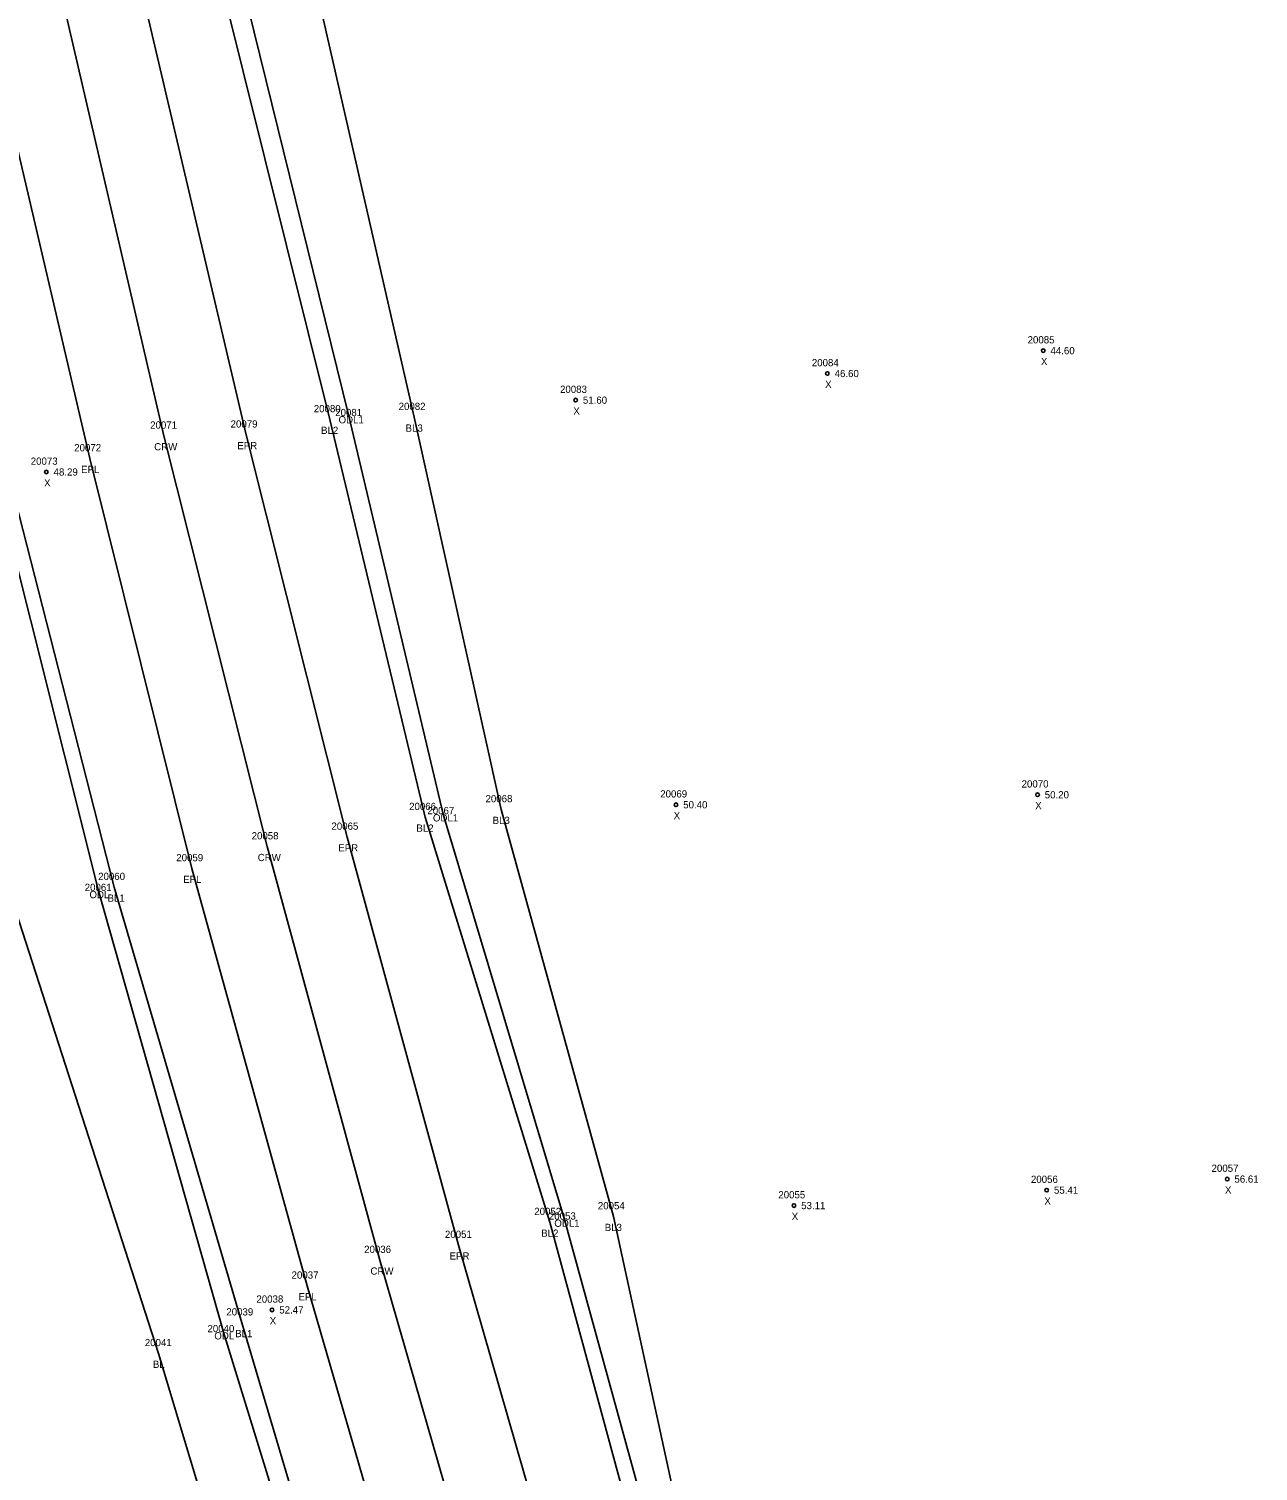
# Model space of a CAD drawing. Extents: x 2445178 to 2446260, y 791158 to 792318.
# Drawn here: x 2445750.9 to 2445920.9, y 791354.3 to 791553.6 of the extents above; entities that cross this region are included whole.
import ezdxf

# ---------------------------------------------------------------- set-up
doc = ezdxf.new("R2010")
doc.units = 0
for name, color, linetype in [('RD_DTM_BkLn1', 7, 'Continuous'), ('RD_EX_H2O', 7, 'Continuous'), ('RD_EX_H2O_txCode', 7, 'Continuous'), ('RD_EX_Road', 7, 'Continuous'), ('RD_EX_Road_txCode', 7, 'Continuous'), ('RD_Sketch8', 7, 'Continuous'), ('RD_SMD_Locator', 7, 'Continuous'), ('RD_SMD_Misc', 7, 'Continuous')]:
    doc.layers.add(name, color=color, linetype=linetype)

msp = doc.modelspace()

# ---------------------------------------------------------------- linework, layer by layer
at = {"layer": 'RD_DTM_BkLn1'}
for points in [[(2445860.1, 791179.04), (2445833.11, 791268.21), (2445816.53, 791324.11), (2445799.46, 791383.44), (2445783.89, 791440.59), (2445769.57, 791497.35), (2445755.95, 791556.11), (2445741.36, 791625.36), (2445732.84, 791671.31), (2445721.28, 791739.8), (2445717.39, 791765.43)], [(2445882.78, 791184.78), (2445856.18, 791275.27), (2445839.04, 791329.43), (2445822.96, 791388.68), (2445805.7, 791444.65), (2445792.52, 791499.62), (2445777.56, 791559.78), (2445760.75, 791635.11), (2445757, 791668.89), (2445761.65, 791682.26), (2445806.3, 791698.85), (2445844.78, 791714.67)], [(2445896.2, 791187.37), (2445865.75, 791277.36), (2445863.45, 791286.42), (2445844.64, 791330.14), (2445831.75, 791389.47), (2445816.24, 791445.72), (2445804.21, 791499.93), (2445790.09, 791561.7), (2445779.57, 791613.54), (2445773.51, 791630.61), (2445764.7, 791668.39), (2445768.27, 791675.25), (2445808.12, 791695.24), (2445844.78, 791714.67)], [(2445839.71, 791171.21), (2445812.99, 791261.63), (2445797.26, 791317.94), (2445780.39, 791374.8), (2445762.73, 791434.98), (2445748.42, 791490.93), (2445737.04, 791541.96), (2445736.07, 791553.56), (2445730.12, 791555.63), (2445697.6, 791546.96), (2445670.73, 791536.08)], [(2445828.38, 791169.47), (2445802.46, 791258.37), (2445786.04, 791313.32), (2445768.83, 791370.56), (2445749.12, 791431.66), (2445737.78, 791488.28), (2445729.51, 791541.48), (2445729.31, 791548.76), (2445698.8, 791542.8), (2445670.73, 791536.08)]]:
    msp.add_lwpolyline(points, dxfattribs=at)
at = {"layer": 'RD_EX_H2O'}
for points in [[(2445885.63, 791185.34), (2445858.54, 791275.66), (2445841.27, 791329.71), (2445824.98, 791389.05), (2445808.2, 791445.07), (2445795.15, 791500.08), (2445780.4, 791559.92), (2445764.43, 791632.51), (2445759.72, 791668.56), (2445764.88, 791679.11), (2445806.8, 791696.09), (2445844.78, 791714.67)], [(2445837.89, 791170.92), (2445811.42, 791261.06), (2445795.3, 791316.79), (2445777.82, 791373.49), (2445760.55, 791434.46), (2445746.47, 791490.55), (2445734.66, 791541.55), (2445732.29, 791551.98), (2445698.31, 791545.12), (2445670.73, 791536.08)]]:
    msp.add_lwpolyline(points, dxfattribs=at)
at = {"layer": 'RD_EX_Road'}
for points in [[(2445850.42, 791174.36), (2445823.13, 791264.7), (2445806.34, 791321.46), (2445789.41, 791379.89), (2445773.46, 791437.57), (2445759.36, 791494.22), (2445744.01, 791559.83), (2445740.09, 791577.64), (2445731.05, 791621.01), (2445722.21, 791669.43), (2445711, 791738.26), (2445706.49, 791765.2)], [(2445870.82, 791182.02), (2445844.02, 791271.27), (2445827.31, 791326.39), (2445810.32, 791385.52), (2445794.94, 791441.92), (2445780.98, 791497.5), (2445766.72, 791558.1), (2445751.9, 791628.3), (2445743.63, 791673.52), (2445732.07, 791741.61), (2445728.16, 791765.65)]]:
    msp.add_lwpolyline(points, dxfattribs=at)
at = {"layer": 'RD_SMD_Locator'}
for centre, radius in [((2445891.16, 791509.13), 0.25), ((2445861.32, 791505.97), 0.25), ((2445826.52, 791502.29), 0.25), ((2445792.52, 791499.62), 0.001), ((2445795.15, 791500.08), 0.001), ((2445804.21, 791499.93), 0.001), ((2445780.98, 791497.5), 0.001), ((2445769.57, 791497.35), 0.001), ((2445759.36, 791494.22), 0.001), ((2445753.35, 791492.36), 0.25), ((2445890.37, 791447.76), 0.25), ((2445816.24, 791445.72), 0.001), ((2445840.39, 791446.38), 0.25), ((2445805.7, 791444.65), 0.001), ((2445808.2, 791445.07), 0.001), ((2445794.94, 791441.92), 0.001), ((2445783.89, 791440.59), 0.001), ((2445773.46, 791437.57), 0.001), ((2445760.55, 791434.46), 0.001), ((2445762.73, 791434.98), 0.001), ((2445916.59, 791394.65), 0.25), ((2445891.64, 791393.12), 0.25), ((2445856.7, 791390.99), 0.25), ((2445822.96, 791388.68), 0.001), ((2445824.98, 791389.05), 0.001), ((2445831.75, 791389.47), 0.001), ((2445810.32, 791385.52), 0.001), ((2445799.46, 791383.44), 0.001), ((2445789.41, 791379.89), 0.001), ((2445784.55, 791376.57), 0.25), ((2445780.39, 791374.8), 0.001), ((2445777.82, 791373.49), 0.001), ((2445768.83, 791370.56), 0.001)]:
    msp.add_circle(centre, radius, dxfattribs=at)

# ---------------------------------------------------------------- texts
at = {"layer": 'RD_EX_H2O_txCode'}
for s, p in [('20081', (2445793.28, 791500.08)), ('ODL1', (2445793.74, 791499.08)), ('20067', (2445806.02, 791445.07)), ('ODL1', (2445806.79, 791444.07)), ('20061', (2445758.65, 791434.46)), ('ODL', (2445759.31, 791433.46)), ('20053', (2445822.82, 791389.05)), ('ODL1', (2445823.57, 791388.05)), ('20040', (2445775.62, 791373.49)), ('ODL', (2445776.57, 791372.49))]:
    msp.add_text(s, height=1, dxfattribs=at).set_placement(p)
at = {"layer": 'RD_EX_Road_txCode'}
for s, p in [('20079', (2445778.82, 791498.5)), ('20072', (2445757.2, 791495.22)), ('EPR', (2445779.75, 791495.5)), ('EPL', (2445758.15, 791492.22)), ('20065', (2445792.76, 791442.92)), ('EPR', (2445793.71, 791439.92)), ('20059', (2445771.31, 791438.57)), ('EPL', (2445772.26, 791435.57)), ('20051', (2445808.45, 791386.52)), ('EPR', (2445809.09, 791383.52)), ('20037', (2445787.25, 791380.89)), ('EPL', (2445788.21, 791377.89))]:
    msp.add_text(s, height=1, dxfattribs=at).set_placement(p)
at = {"layer": 'RD_Sketch8'}
for s, p in [('20085', (2445889, 791510.13)), ('44.60', (2445892.16, 791508.63)), ('20084', (2445859.17, 791506.97)), ('X', (2445890.84, 791507.13)), ('46.60', (2445862.32, 791505.47)), ('20083', (2445824.36, 791503.29)), ('X', (2445861.01, 791503.97)), ('51.60', (2445827.52, 791501.79)), ('X', (2445826.2, 791500.29)), ('20073', (2445751.19, 791493.36)), ('48.29', (2445754.35, 791491.86)), ('X', (2445753.04, 791490.36)), ('20070', (2445888.17, 791448.76)), ('20069', (2445838.21, 791447.38)), ('50.20', (2445891.37, 791447.26)), ('50.40', (2445841.39, 791445.88)), ('X', (2445890.05, 791445.76)), ('X', (2445840.07, 791444.38)), ('20057', (2445914.43, 791395.65)), ('20056', (2445889.46, 791394.12)), ('56.61', (2445917.59, 791394.15)), ('20055', (2445854.54, 791391.99)), ('X', (2445891.32, 791391.12)), ('55.41', (2445892.64, 791392.62)), ('X', (2445916.28, 791392.65)), ('X', (2445856.39, 791388.99)), ('53.11', (2445857.7, 791390.49)), ('20038', (2445782.39, 791377.57)), ('52.47', (2445785.55, 791376.07)), ('X', (2445784.23, 791374.57))]:
    msp.add_text(s, height=1, dxfattribs=at).set_placement(p)
at = {"layer": 'RD_SMD_Misc'}
for s, p in [('20080', (2445790.32, 791500.62)), ('20082', (2445802.05, 791500.93)), ('20071', (2445767.7, 791498.35)), ('BL2', (2445791.32, 791497.62)), ('BL3', (2445803.01, 791497.93)), ('CRW', (2445768.26, 791495.35)), ('20068', (2445814.06, 791446.72)), ('20066', (2445803.5, 791445.65)), ('BL2', (2445804.5, 791442.65)), ('BL3', (2445815.04, 791443.72)), ('20058', (2445781.73, 791441.59)), ('CRW', (2445782.57, 791438.59)), ('20060', (2445760.51, 791435.98)), ('BL1', (2445761.81, 791432.98)), ('20052', (2445820.8, 791389.68)), ('20054', (2445829.59, 791390.47)), ('BL3', (2445830.54, 791387.47)), ('BL2', (2445821.76, 791386.68)), ('20036', (2445797.28, 791384.44)), ('CRW', (2445798.15, 791381.44)), ('20039', (2445778.23, 791375.8)), ('20041', (2445766.96, 791371.56)), ('BL1', (2445779.46, 791372.8)), ('BL', (2445768.08, 791368.56))]:
    msp.add_text(s, height=1, dxfattribs=at).set_placement(p)

doc.saveas('drawing.dxf')
